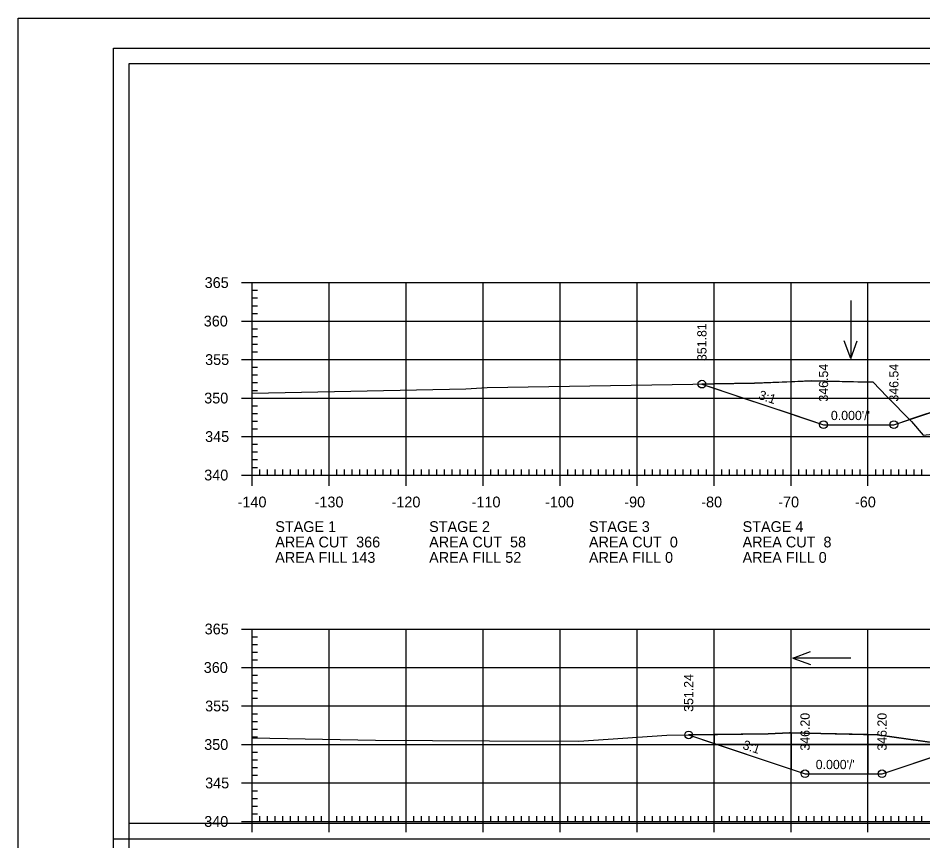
# Model space of a CAD drawing. Extents: x 1368910 to 1369601, y 380116 to 380950.
# Drawn here: x 1369267.2 to 1369384.7, y 380416.9 to 380523.8 of the extents above; entities that cross this region are included whole.
import ezdxf

# ---------------------------------------------------------------- set-up
doc = ezdxf.new("R2010")
doc.units = 0
for name, color, linetype in [('_STAGE 1 CUT', 7, 'Continuous'), ('_STAGE 1 FILL', 7, 'Continuous'), ('R_Axis', 7, 'Continuous'), ('R_Axis Annot', 7, 'Continuous'), ('R_Border', 7, 'Continuous'), ('R_Border Plan-Plan', 7, 'Continuous'), ('R_Exist Surface', 7, 'Continuous'), ('R_Fin Surface', 7, 'Continuous'), ('R_Grid', 7, 'Continuous'), ('R_No Plot', 7, 'Continuous'), ('R_Water Annot', 7, 'Continuous'), ('R_Xsect Elev', 7, 'Continuous'), ('R_Xsect Slope', 7, 'Continuous')]:
    doc.layers.add(name, color=color, linetype=linetype)

msp = doc.modelspace()

# ---------------------------------------------------------------- linework, layer by layer
at = {"layer": '_STAGE 1 CUT'}
for p, q in [((1369380.95, 380470.96), (1369382.96, 380471.63)), ((1369371.48, 380430.85), (1369367.59, 380430.94)), ((1369367.59, 380430.94), (1369367.59, 380429.42)), ((1369367.59, 380429.42), (1369367.59, 380430.94)), ((1369357.59, 380430.71), (1369354.29, 380430.66)), ((1369354.29, 380430.66), (1369357.59, 380429.56)), ((1369357.59, 380430.71), (1369357.59, 380429.56)), ((1369357.59, 380429.56), (1369357.59, 380430.71)), ((1369377.59, 380430.72), (1369371.48, 380430.85)), ((1369378.84, 380430.69), (1369377.59, 380430.72)), ((1369377.59, 380430.72), (1369377.59, 380429.42)), ((1369377.59, 380429.42), (1369377.59, 380430.72)), ((1369387.59, 380429.44), (1369378.84, 380430.69)), ((1369357.59, 380429.56), (1369358.01, 380429.42)), ((1369367.59, 380429.42), (1369358.01, 380429.42)), ((1369358.01, 380429.42), (1369367.59, 380426.23)), ((1369358.01, 380429.42), (1369367.59, 380429.42)), ((1369367.59, 380429.42), (1369377.59, 380429.42)), ((1369377.59, 380429.42), (1369367.59, 380429.42)), ((1369367.59, 380429.42), (1369367.59, 380426.23)), ((1369367.59, 380426.23), (1369367.59, 380429.42)), ((1369387.59, 380429.42), (1369377.59, 380429.42)), ((1369377.59, 380429.42), (1369377.59, 380425.62)), ((1369377.59, 380429.42), (1369387.59, 380429.42)), ((1369377.59, 380425.62), (1369377.59, 380429.42)), ((1369379.42, 380425.62), (1369387.59, 380428.35)), ((1369367.59, 380426.23), (1369369.41, 380425.62)), ((1369369.41, 380425.62), (1369377.59, 380425.62)), ((1369377.59, 380425.62), (1369379.23, 380425.62))]:
    msp.add_line(p, q, dxfattribs=at)
for points in [[(1369382.96, 380471.63), (1369380.24, 380474.42), (1369380.05, 380474.61), (1369378.24, 380476.47), (1369377.59, 380476.49), (1369370.22, 380476.65), (1369367.59, 380476.54), (1369362.84, 380476.34), (1369357.59, 380476.26), (1369356.01, 380476.23)], [(1369356.01, 380476.23), (1369357.59, 380475.7), (1369361.43, 380474.42), (1369364.17, 380473.51), (1369367.59, 380472.37), (1369371.81, 380470.96), (1369377.59, 380470.96), (1369380.95, 380470.96)], [(1369367.59, 380430.94), (1369367.4, 380430.94), (1369364.61, 380430.82), (1369357.59, 380430.71)], [(1369379.23, 380425.62), (1369379.41, 380425.62), (1369379.42, 380425.62)]]:
    msp.add_lwpolyline(points, dxfattribs=at)
at = {"layer": '_STAGE 1 FILL'}
for points in [[(1369412.86, 380480.22), (1369408.07, 380479.42), (1369407.59, 380479.34), (1369404.59, 380478.84), (1369401.71, 380477.88), (1369397.59, 380476.51), (1369391.33, 380474.42), (1369387.59, 380473.17), (1369382.96, 380471.63)], [(1369382.96, 380471.63), (1369383.22, 380471.36), (1369384.74, 380469.59), (1369387.59, 380469.9), (1369396.43, 380470.84), (1369397.59, 380470.78), (1369400.85, 380470.6), (1369401.71, 380471.02), (1369405.31, 380472.77)]]:
    msp.add_lwpolyline(points, dxfattribs=at)
at = {"layer": 'R_Axis'}
for p, q in [((1369296.19, 380489.42), (1369298.99, 380489.42)), ((1369297.59, 380464.42), (1369297.59, 380489.42)), ((1369297.59, 380488.42), (1369298.29, 380488.42)), ((1369297.59, 380487.42), (1369298.29, 380487.42)), ((1369297.59, 380486.42), (1369298.29, 380486.42)), ((1369297.59, 380485.42), (1369298.29, 380485.42)), ((1369296.19, 380484.42), (1369298.99, 380484.42)), ((1369297.59, 380483.42), (1369298.29, 380483.42)), ((1369297.59, 380482.42), (1369298.29, 380482.42)), ((1369297.59, 380481.42), (1369298.29, 380481.42)), ((1369297.59, 380480.42), (1369298.29, 380480.42)), ((1369296.19, 380479.42), (1369298.99, 380479.42)), ((1369297.59, 380478.42), (1369298.29, 380478.42)), ((1369297.59, 380477.42), (1369298.29, 380477.42)), ((1369297.59, 380476.42), (1369298.29, 380476.42)), ((1369296.19, 380474.42), (1369298.99, 380474.42)), ((1369297.59, 380475.42), (1369298.29, 380475.42)), ((1369297.59, 380473.42), (1369298.29, 380473.42)), ((1369297.59, 380472.42), (1369298.29, 380472.42)), ((1369297.59, 380471.42), (1369298.29, 380471.42)), ((1369297.59, 380470.42), (1369298.29, 380470.42)), ((1369296.19, 380469.42), (1369298.99, 380469.42)), ((1369297.59, 380468.42), (1369298.29, 380468.42)), ((1369297.59, 380467.42), (1369298.29, 380467.42)), ((1369297.59, 380466.42), (1369298.29, 380466.42)), ((1369297.59, 380463.02), (1369297.59, 380465.82)), ((1369297.59, 380465.42), (1369298.29, 380465.42)), ((1369298.59, 380464.42), (1369298.59, 380465.12)), ((1369299.59, 380464.42), (1369299.59, 380465.12)), ((1369300.59, 380464.42), (1369300.59, 380465.12)), ((1369301.59, 380464.42), (1369301.59, 380465.12)), ((1369302.59, 380464.42), (1369302.59, 380465.12)), ((1369303.59, 380464.42), (1369303.59, 380465.12)), ((1369304.59, 380464.42), (1369304.59, 380465.12)), ((1369305.59, 380464.42), (1369305.59, 380465.12)), ((1369306.59, 380464.42), (1369306.59, 380465.12)), ((1369307.59, 380463.02), (1369307.59, 380465.82)), ((1369308.59, 380464.42), (1369308.59, 380465.12)), ((1369309.59, 380464.42), (1369309.59, 380465.12)), ((1369310.59, 380464.42), (1369310.59, 380465.12)), ((1369311.59, 380464.42), (1369311.59, 380465.12)), ((1369312.59, 380464.42), (1369312.59, 380465.12)), ((1369313.59, 380464.42), (1369313.59, 380465.12)), ((1369314.59, 380464.42), (1369314.59, 380465.12)), ((1369315.59, 380464.42), (1369315.59, 380465.12)), ((1369316.59, 380464.42), (1369316.59, 380465.12)), ((1369317.59, 380463.02), (1369317.59, 380465.82)), ((1369318.59, 380464.42), (1369318.59, 380465.12)), ((1369319.59, 380464.42), (1369319.59, 380465.12)), ((1369320.59, 380464.42), (1369320.59, 380465.12)), ((1369321.59, 380464.42), (1369321.59, 380465.12)), ((1369322.59, 380464.42), (1369322.59, 380465.12)), ((1369323.59, 380464.42), (1369323.59, 380465.12)), ((1369324.59, 380464.42), (1369324.59, 380465.12)), ((1369325.59, 380464.42), (1369325.59, 380465.12)), ((1369326.59, 380464.42), (1369326.59, 380465.12)), ((1369327.59, 380463.02), (1369327.59, 380465.82)), ((1369328.59, 380464.42), (1369328.59, 380465.12)), ((1369329.59, 380464.42), (1369329.59, 380465.12)), ((1369330.59, 380464.42), (1369330.59, 380465.12)), ((1369331.59, 380464.42), (1369331.59, 380465.12)), ((1369332.59, 380464.42), (1369332.59, 380465.12)), ((1369333.59, 380464.42), (1369333.59, 380465.12)), ((1369334.59, 380464.42), (1369334.59, 380465.12)), ((1369335.59, 380464.42), (1369335.59, 380465.12)), ((1369336.59, 380464.42), (1369336.59, 380465.12)), ((1369337.59, 380463.02), (1369337.59, 380465.82)), ((1369338.59, 380464.42), (1369338.59, 380465.12)), ((1369339.59, 380464.42), (1369339.59, 380465.12)), ((1369340.59, 380464.42), (1369340.59, 380465.12)), ((1369341.59, 380464.42), (1369341.59, 380465.12)), ((1369342.59, 380464.42), (1369342.59, 380465.12)), ((1369343.59, 380464.42), (1369343.59, 380465.12)), ((1369344.59, 380464.42), (1369344.59, 380465.12)), ((1369345.59, 380464.42), (1369345.59, 380465.12)), ((1369346.59, 380464.42), (1369346.59, 380465.12)), ((1369347.59, 380463.02), (1369347.59, 380465.82)), ((1369348.59, 380464.42), (1369348.59, 380465.12)), ((1369349.59, 380464.42), (1369349.59, 380465.12)), ((1369350.59, 380464.42), (1369350.59, 380465.12)), ((1369351.59, 380464.42), (1369351.59, 380465.12)), ((1369352.59, 380464.42), (1369352.59, 380465.12)), ((1369353.59, 380464.42), (1369353.59, 380465.12)), ((1369354.59, 380464.42), (1369354.59, 380465.12)), ((1369355.59, 380464.42), (1369355.59, 380465.12)), ((1369356.59, 380464.42), (1369356.59, 380465.12)), ((1369357.59, 380463.02), (1369357.59, 380465.82)), ((1369358.59, 380464.42), (1369358.59, 380465.12)), ((1369359.59, 380464.42), (1369359.59, 380465.12)), ((1369360.59, 380464.42), (1369360.59, 380465.12)), ((1369361.59, 380464.42), (1369361.59, 380465.12)), ((1369362.59, 380464.42), (1369362.59, 380465.12)), ((1369363.59, 380464.42), (1369363.59, 380465.12)), ((1369364.59, 380464.42), (1369364.59, 380465.12)), ((1369365.59, 380464.42), (1369365.59, 380465.12)), ((1369366.59, 380464.42), (1369366.59, 380465.12)), ((1369367.59, 380463.02), (1369367.59, 380465.82)), ((1369368.59, 380464.42), (1369368.59, 380465.12)), ((1369369.59, 380464.42), (1369369.59, 380465.12)), ((1369370.59, 380464.42), (1369370.59, 380465.12)), ((1369371.59, 380464.42), (1369371.59, 380465.12)), ((1369372.59, 380464.42), (1369372.59, 380465.12)), ((1369373.59, 380464.42), (1369373.59, 380465.12)), ((1369374.59, 380464.42), (1369374.59, 380465.12)), ((1369375.59, 380464.42), (1369375.59, 380465.12)), ((1369376.59, 380464.42), (1369376.59, 380465.12)), ((1369377.59, 380463.02), (1369377.59, 380465.82)), ((1369378.59, 380464.42), (1369378.59, 380465.12)), ((1369379.59, 380464.42), (1369379.59, 380465.12)), ((1369380.59, 380464.42), (1369380.59, 380465.12)), ((1369381.59, 380464.42), (1369381.59, 380465.12)), ((1369382.59, 380464.42), (1369382.59, 380465.12)), ((1369383.59, 380464.42), (1369383.59, 380465.12)), ((1369384.59, 380464.42), (1369384.59, 380465.12)), ((1369296.19, 380464.42), (1369298.99, 380464.42)), ((1369297.59, 380464.42), (1369577.59, 380464.42)), ((1369296.19, 380444.42), (1369298.99, 380444.42)), ((1369297.59, 380419.42), (1369297.59, 380444.42)), ((1369297.59, 380443.42), (1369298.29, 380443.42)), ((1369297.59, 380442.42), (1369298.29, 380442.42)), ((1369297.59, 380441.42), (1369298.29, 380441.42)), ((1369297.59, 380440.42), (1369298.29, 380440.42)), ((1369296.19, 380439.42), (1369298.99, 380439.42)), ((1369297.59, 380438.42), (1369298.29, 380438.42)), ((1369297.59, 380437.42), (1369298.29, 380437.42)), ((1369297.59, 380436.42), (1369298.29, 380436.42)), ((1369296.19, 380434.42), (1369298.99, 380434.42)), ((1369297.59, 380435.42), (1369298.29, 380435.42)), ((1369297.59, 380433.42), (1369298.29, 380433.42)), ((1369297.59, 380432.42), (1369298.29, 380432.42)), ((1369297.59, 380431.42), (1369298.29, 380431.42)), ((1369297.59, 380430.42), (1369298.29, 380430.42)), ((1369296.19, 380429.42), (1369298.99, 380429.42)), ((1369297.59, 380428.42), (1369298.29, 380428.42)), ((1369297.59, 380427.42), (1369298.29, 380427.42)), ((1369297.59, 380426.42), (1369298.29, 380426.42)), ((1369297.59, 380425.42), (1369298.29, 380425.42)), ((1369296.19, 380424.42), (1369298.99, 380424.42)), ((1369297.59, 380423.42), (1369298.29, 380423.42)), ((1369297.59, 380422.42), (1369298.29, 380422.42)), ((1369297.59, 380421.42), (1369298.29, 380421.42)), ((1369297.59, 380418.02), (1369297.59, 380420.82)), ((1369297.59, 380420.42), (1369298.29, 380420.42)), ((1369307.59, 380418.02), (1369307.59, 380420.82)), ((1369317.59, 380418.02), (1369317.59, 380420.82)), ((1369327.59, 380418.02), (1369327.59, 380420.82)), ((1369337.59, 380418.02), (1369337.59, 380420.82)), ((1369347.59, 380418.02), (1369347.59, 380420.82)), ((1369357.59, 380418.02), (1369357.59, 380420.82)), ((1369367.59, 380418.02), (1369367.59, 380420.82)), ((1369377.59, 380418.02), (1369377.59, 380420.82)), ((1369296.19, 380419.42), (1369298.99, 380419.42)), ((1369297.59, 380419.42), (1369577.59, 380419.42)), ((1369298.59, 380419.42), (1369298.59, 380420.12)), ((1369299.59, 380419.42), (1369299.59, 380420.12)), ((1369300.59, 380419.42), (1369300.59, 380420.12)), ((1369301.59, 380419.42), (1369301.59, 380420.12)), ((1369302.59, 380419.42), (1369302.59, 380420.12)), ((1369303.59, 380419.42), (1369303.59, 380420.12)), ((1369304.59, 380419.42), (1369304.59, 380420.12)), ((1369305.59, 380419.42), (1369305.59, 380420.12)), ((1369306.59, 380419.42), (1369306.59, 380420.12)), ((1369308.59, 380419.42), (1369308.59, 380420.12)), ((1369309.59, 380419.42), (1369309.59, 380420.12)), ((1369310.59, 380419.42), (1369310.59, 380420.12)), ((1369311.59, 380419.42), (1369311.59, 380420.12)), ((1369312.59, 380419.42), (1369312.59, 380420.12)), ((1369313.59, 380419.42), (1369313.59, 380420.12)), ((1369314.59, 380419.42), (1369314.59, 380420.12)), ((1369315.59, 380419.42), (1369315.59, 380420.12)), ((1369316.59, 380419.42), (1369316.59, 380420.12)), ((1369318.59, 380419.42), (1369318.59, 380420.12)), ((1369319.59, 380419.42), (1369319.59, 380420.12)), ((1369320.59, 380419.42), (1369320.59, 380420.12)), ((1369321.59, 380419.42), (1369321.59, 380420.12)), ((1369322.59, 380419.42), (1369322.59, 380420.12)), ((1369323.59, 380419.42), (1369323.59, 380420.12)), ((1369324.59, 380419.42), (1369324.59, 380420.12)), ((1369325.59, 380419.42), (1369325.59, 380420.12)), ((1369326.59, 380419.42), (1369326.59, 380420.12)), ((1369328.59, 380419.42), (1369328.59, 380420.12)), ((1369329.59, 380419.42), (1369329.59, 380420.12)), ((1369330.59, 380419.42), (1369330.59, 380420.12)), ((1369331.59, 380419.42), (1369331.59, 380420.12)), ((1369332.59, 380419.42), (1369332.59, 380420.12)), ((1369333.59, 380419.42), (1369333.59, 380420.12)), ((1369334.59, 380419.42), (1369334.59, 380420.12)), ((1369335.59, 380419.42), (1369335.59, 380420.12)), ((1369336.59, 380419.42), (1369336.59, 380420.12)), ((1369338.59, 380419.42), (1369338.59, 380420.12)), ((1369339.59, 380419.42), (1369339.59, 380420.12)), ((1369340.59, 380419.42), (1369340.59, 380420.12)), ((1369341.59, 380419.42), (1369341.59, 380420.12)), ((1369342.59, 380419.42), (1369342.59, 380420.12)), ((1369343.59, 380419.42), (1369343.59, 380420.12)), ((1369344.59, 380419.42), (1369344.59, 380420.12)), ((1369345.59, 380419.42), (1369345.59, 380420.12)), ((1369346.59, 380419.42), (1369346.59, 380420.12)), ((1369348.59, 380419.42), (1369348.59, 380420.12)), ((1369349.59, 380419.42), (1369349.59, 380420.12)), ((1369350.59, 380419.42), (1369350.59, 380420.12)), ((1369351.59, 380419.42), (1369351.59, 380420.12)), ((1369352.59, 380419.42), (1369352.59, 380420.12)), ((1369353.59, 380419.42), (1369353.59, 380420.12)), ((1369354.59, 380419.42), (1369354.59, 380420.12)), ((1369355.59, 380419.42), (1369355.59, 380420.12)), ((1369356.59, 380419.42), (1369356.59, 380420.12)), ((1369358.59, 380419.42), (1369358.59, 380420.12)), ((1369359.59, 380419.42), (1369359.59, 380420.12)), ((1369360.59, 380419.42), (1369360.59, 380420.12)), ((1369361.59, 380419.42), (1369361.59, 380420.12)), ((1369362.59, 380419.42), (1369362.59, 380420.12)), ((1369363.59, 380419.42), (1369363.59, 380420.12)), ((1369364.59, 380419.42), (1369364.59, 380420.12)), ((1369365.59, 380419.42), (1369365.59, 380420.12)), ((1369366.59, 380419.42), (1369366.59, 380420.12)), ((1369368.59, 380419.42), (1369368.59, 380420.12)), ((1369369.59, 380419.42), (1369369.59, 380420.12)), ((1369370.59, 380419.42), (1369370.59, 380420.12)), ((1369371.59, 380419.42), (1369371.59, 380420.12)), ((1369372.59, 380419.42), (1369372.59, 380420.12)), ((1369373.59, 380419.42), (1369373.59, 380420.12)), ((1369374.59, 380419.42), (1369374.59, 380420.12)), ((1369375.59, 380419.42), (1369375.59, 380420.12)), ((1369376.59, 380419.42), (1369376.59, 380420.12)), ((1369378.59, 380419.42), (1369378.59, 380420.12)), ((1369379.59, 380419.42), (1369379.59, 380420.12)), ((1369380.59, 380419.42), (1369380.59, 380420.12)), ((1369381.59, 380419.42), (1369381.59, 380420.12)), ((1369382.59, 380419.42), (1369382.59, 380420.12)), ((1369383.59, 380419.42), (1369383.59, 380420.12)), ((1369384.59, 380419.42), (1369384.59, 380420.12))]:
    msp.add_line(p, q, dxfattribs=at)
at = {"layer": 'R_Border'}
for p, q in [((1369279.59, 380519.88), (1369595.77, 380519.88)), ((1369279.59, 380314.42), (1369279.59, 380519.88))]:
    msp.add_line(p, q, dxfattribs=at)
at = {"layer": 'R_Border Plan-Plan'}
msp.add_line((1369279.59, 380417.15), (1369595.77, 380417.15), dxfattribs=at)
at = {"layer": 'R_Exist Surface'}
for points in [[(1369297.59, 380475.04), (1369325.34, 380475.61), (1369328.12, 380475.79), (1369362.84, 380476.34), (1369370.22, 380476.65), (1369378.24, 380476.47), (1369380.05, 380474.61), (1369383.22, 380471.36), (1369384.74, 380469.59)], [(1369297.59, 380430.28), (1369313.63, 380429.96), (1369328.42, 380429.88), (1369340.01, 380429.87), (1369351.47, 380430.62), (1369364.61, 380430.82), (1369367.4, 380430.94), (1369371.48, 380430.85), (1369378.84, 380430.69), (1369388.43, 380429.32)]]:
    msp.add_lwpolyline(points, dxfattribs=at)
at = {"layer": 'R_Fin Surface'}
for points in [[(1369356.01, 380476.23), (1369364.17, 380473.51), (1369371.81, 380470.96), (1369380.95, 380470.96), (1369404.59, 380478.84), (1369412.86, 380480.22), (1369418.59, 380481.17), (1369426.59, 380481.49), (1369437.59, 380481.71), (1369448.59, 380481.49), (1369456.59, 380481.17), (1369463.18, 380480.2), (1369470.59, 380479.11), (1369491.01, 380472.3), (1369498.44, 380472.3), (1369504.57, 380474.35), (1369512.93, 380477.13)], [(1369354.29, 380430.66), (1369369.41, 380425.62), (1369379.41, 380425.62), (1369404.59, 380434.01), (1369412.86, 380435.39), (1369418.59, 380436.35), (1369426.59, 380436.67), (1369437.59, 380436.89), (1369448.59, 380436.67), (1369456.59, 380436.35), (1369462.32, 380435.39), (1369470.59, 380434.01), (1369485.66, 380428.99), (1369490.58, 380428.99), (1369494.23, 380430.21)]]:
    msp.add_lwpolyline(points, dxfattribs=at)
at = {"layer": 'R_Grid'}
for p, q in [((1369297.59, 380489.42), (1369577.59, 380489.42)), ((1369297.59, 380464.42), (1369297.59, 380489.42)), ((1369307.59, 380464.42), (1369307.59, 380489.42)), ((1369317.59, 380464.42), (1369317.59, 380489.42)), ((1369327.59, 380464.42), (1369327.59, 380489.42)), ((1369337.59, 380464.42), (1369337.59, 380489.42)), ((1369347.59, 380464.42), (1369347.59, 380489.42)), ((1369357.59, 380464.42), (1369357.59, 380489.42)), ((1369367.59, 380464.42), (1369367.59, 380489.42)), ((1369377.59, 380464.42), (1369377.59, 380489.42)), ((1369297.59, 380484.42), (1369577.59, 380484.42)), ((1369297.59, 380479.42), (1369577.59, 380479.42)), ((1369297.59, 380474.42), (1369577.59, 380474.42)), ((1369297.59, 380469.42), (1369577.59, 380469.42)), ((1369297.59, 380464.42), (1369577.59, 380464.42)), ((1369297.59, 380444.42), (1369577.59, 380444.42)), ((1369297.59, 380419.42), (1369297.59, 380444.42)), ((1369297.59, 380444.42), (1369577.59, 380444.42)), ((1369297.59, 380419.42), (1369297.59, 380444.42)), ((1369307.59, 380419.42), (1369307.59, 380444.42)), ((1369307.59, 380419.42), (1369307.59, 380444.42)), ((1369317.59, 380419.42), (1369317.59, 380444.42)), ((1369317.59, 380419.42), (1369317.59, 380444.42)), ((1369327.59, 380419.42), (1369327.59, 380444.42)), ((1369327.59, 380419.42), (1369327.59, 380444.42)), ((1369337.59, 380419.42), (1369337.59, 380444.42)), ((1369337.59, 380419.42), (1369337.59, 380444.42)), ((1369347.59, 380419.42), (1369347.59, 380444.42)), ((1369347.59, 380419.42), (1369347.59, 380444.42)), ((1369357.59, 380419.42), (1369357.59, 380444.42)), ((1369357.59, 380419.42), (1369357.59, 380444.42)), ((1369367.59, 380419.42), (1369367.59, 380444.42)), ((1369367.59, 380419.42), (1369367.59, 380444.42)), ((1369377.59, 380419.42), (1369377.59, 380444.42)), ((1369377.59, 380419.42), (1369377.59, 380444.42)), ((1369297.59, 380439.42), (1369577.59, 380439.42)), ((1369297.59, 380439.42), (1369577.59, 380439.42)), ((1369297.59, 380434.42), (1369577.59, 380434.42)), ((1369297.59, 380434.42), (1369577.59, 380434.42)), ((1369297.59, 380429.42), (1369577.59, 380429.42)), ((1369297.59, 380429.42), (1369577.59, 380429.42)), ((1369297.59, 380424.42), (1369577.59, 380424.42)), ((1369297.59, 380424.42), (1369577.59, 380424.42)), ((1369297.59, 380419.42), (1369577.59, 380419.42)), ((1369297.59, 380419.42), (1369577.59, 380419.42))]:
    msp.add_line(p, q, dxfattribs=at)
at = {"layer": 'R_No Plot'}
for points in [[(1369267.18, 380523.78), (1369600.52, 380523.78), (1369600.52, 380310.44), (1369267.18, 380310.44)], [(1369593.77, 380419.15), (1369281.59, 380419.15), (1369281.59, 380517.88), (1369531.13, 380517.88), (1369531.13, 380508), (1369548.67, 380508), (1369572.77, 380508), (1369572.77, 380485.67), (1369593.77, 380485.67)], [(1369281.59, 380517.88), (1369531.13, 380517.88), (1369531.13, 380508), (1369548.67, 380508), (1369572.77, 380508), (1369572.77, 380485.67), (1369593.77, 380485.67), (1369593.77, 380316.42), (1369281.59, 380316.42)]]:
    msp.add_lwpolyline(points, close=True, dxfattribs=at)
for centre in [(1369356.01, 380476.23), (1369371.81, 380470.96), (1369380.95, 380470.96), (1369354.29, 380430.66), (1369369.41, 380425.62), (1369379.41, 380425.62)]:
    msp.add_circle(centre, 0.5, dxfattribs=at)
at = {"layer": 'R_Water Annot'}
for p, q in [((1369375.35, 380487.08), (1369375.35, 380479.54)), ((1369375.35, 380479.54), (1369374.51, 380481.85)), ((1369375.35, 380479.54), (1369376.19, 380481.85)), ((1369367.81, 380440.65), (1369370.12, 380441.49)), ((1369375.35, 380440.65), (1369367.81, 380440.65)), ((1369367.81, 380440.65), (1369370.12, 380439.81))]:
    msp.add_line(p, q, dxfattribs=at)

# ---------------------------------------------------------------- texts
at = {"layer": 'R_Axis Annot'}
for s, p in [('365', (1369291.42, 380488.72)), ('360', (1369291.3, 380483.72)), ('355', (1369291.48, 380478.72)), ('350', (1369291.36, 380473.72)), ('345', (1369291.48, 380468.72)), ('340', (1369291.36, 380463.72)), ('-140', (1369295.7, 380460.22)), ('-130', (1369305.7, 380460.22)), ('-120', (1369315.7, 380460.22)), ('-110', (1369326.1, 380460.22)), ('-100', (1369335.64, 380460.22)), ('-90', (1369345.93, 380460.22)), ('-80', (1369355.93, 380460.22)), ('-70', (1369365.93, 380460.22)), ('-60', (1369375.9, 380460.22)), ('STAGE 1', (1369300.59, 380457.02)), ('STAGE 2', (1369320.58, 380457.02)), ('STAGE 3', (1369341.34, 380457.02)), ('STAGE 4', (1369361.3, 380457.02)), ('AREA CUT  366', (1369300.59, 380455.02)), ('AREA CUT  58', (1369320.58, 380455.02)), ('AREA CUT  0', (1369341.34, 380455.02)), ('AREA CUT  8', (1369361.3, 380455.02)), ('AREA FILL 143', (1369300.59, 380453.02)), ('AREA FILL 52', (1369320.58, 380453.02)), ('AREA FILL 0', (1369341.34, 380453.02)), ('AREA FILL 0', (1369361.3, 380453.02)), ('365', (1369291.42, 380443.72)), ('360', (1369291.3, 380438.72)), ('355', (1369291.48, 380433.72)), ('350', (1369291.36, 380428.72)), ('345', (1369291.48, 380423.72)), ('340', (1369291.36, 380418.72))]:
    msp.add_text(s, height=1.4, dxfattribs=at).set_placement(p)
at = {"layer": 'R_Xsect Elev'}
for s, p in [('351.81', (1369356.61, 380479.23)), ('346.54', (1369372.41, 380473.96)), ('346.54', (1369381.55, 380473.96)), ('351.24', (1369354.89, 380433.66)), ('346.20', (1369370.01, 380428.62)), ('346.20', (1369380.01, 380428.62))]:
    msp.add_text(s, height=1.2, rotation=90, dxfattribs=at).set_placement(p)
at = {"layer": 'R_Xsect Slope'}
for s, rotation, p in [('3:1', 341.5651, (1369363.28, 380474.33)), ("0.000'/'", 360, (1369372.77, 380471.56)), ('3:1', 341.5651, (1369361.22, 380428.88)), ("0.000'/'", 360, (1369370.8, 380426.22))]:
    msp.add_text(s, height=1.2, rotation=rotation, dxfattribs=at).set_placement(p)

doc.saveas('drawing.dxf')
